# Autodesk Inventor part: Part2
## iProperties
Created: 2002-04
Part Number: Part2
Material: Aluminum-6061
Document SubType Name: Sheet Metal
Control State: 0
Master: False
Checked Out: False
Shininess: 77.0
Angle Display Precision: 2
Document Length Units: 11269
Document Angle Units: 11279
Document Time Units: 11290
Document Mass Units: 11283
Document Length Units Precision: 3
Document Angle Units Precision: 2
Density: 0.0
Volumn: 0.0
Area: 0.0
PropertySet Name: Model Information
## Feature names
1. Plate1
